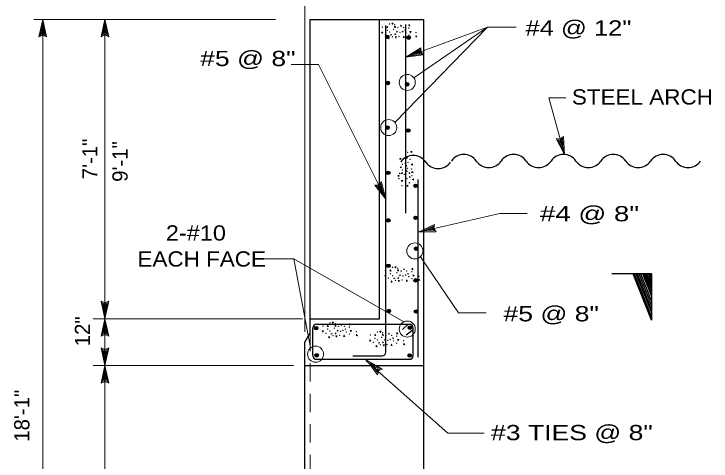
# Model space of a CAD drawing. Extents: x -28.1 to 13.9, y -16.1 to 13.9.
# Drawn here: x -18.11 to -12.4, y 6.4 to 10.06 of the extents above; entities that cross this region are included whole.
import ezdxf
from ezdxf.enums import TextEntityAlignment as Align

# ---------------------------------------------------------------- set-up
doc = ezdxf.new("R2010")
doc.units = 0
doc.header["$LTSCALE"] = 0.05
doc.linetypes.add('MEDIUM_DASHED', pattern=[4.5, 3, -1.5])
doc.layers.add('1', color=7, linetype='Continuous', lineweight=13)
doc.layers.add('2', color=7, linetype='Continuous', lineweight=13)

msp = doc.modelspace()

# ---------------------------------------------------------------- linework, layer by layer
at = {"layer": '1'}
for p, q in [((-15.72804, 7.45469), (-15.72804, 11.00169)), ((-15.96804, 10.01569), (-17.94604, 10.01569)), ((-17.87304, 10.01569), (-17.90404, 9.87169)), ((-17.87304, 3.39369), (-17.87304, 10.01569)), ((-17.87304, 10.01569), (-17.84204, 9.87169)), ((-17.36404, 10.01769), (-17.39504, 9.87369)), ((-17.36404, 10.01769), (-17.33304, 9.87369)), ((-17.87304, 9.97869), (-17.89304, 9.88469)), ((-17.87304, 9.94269), (-17.88204, 9.89769)), ((-17.87304, 9.97869), (-17.85304, 9.88469)), ((-17.87304, 9.94269), (-17.86304, 9.89769)), ((-17.36404, 9.98069), (-17.38404, 9.88669)), ((-17.36404, 9.94469), (-17.37304, 9.89969)), ((-17.36404, 9.98069), (-17.34404, 9.88669)), ((-17.36404, 9.94469), (-17.35404, 9.89969)), ((-14.90004, 9.70469), (-14.23204, 9.95169)), ((-14.83404, 9.53569), (-14.23204, 9.95169)), ((-17.87304, 9.89369), (-17.89304, 9.88469)), ((-17.87304, 9.90169), (-17.88204, 9.89769)), ((-17.86304, 9.89769), (-17.87304, 9.90169)), ((-17.85304, 9.88469), (-17.87304, 9.89369)), ((-17.36404, 9.89569), (-17.38404, 9.88669)), ((-17.36404, 9.90369), (-17.37304, 9.89969)), ((-17.35404, 9.89969), (-17.36404, 9.90369)), ((-17.34404, 9.88669), (-17.36404, 9.89569)), ((-14.90004, 9.70469), (-14.77604, 9.78369)), ((-14.86504, 9.71769), (-14.78404, 9.76869)), ((-14.78404, 9.76869), (-14.78604, 9.74669)), ((-14.90004, 9.70469), (-14.75404, 9.72569)), ((-14.86504, 9.71769), (-14.77004, 9.73169)), ((-14.83204, 9.72969), (-14.79304, 9.75469)), ((-14.83204, 9.72969), (-14.78604, 9.73669)), ((-14.79304, 9.75469), (-14.79304, 9.74469)), ((-14.79304, 9.74469), (-14.78604, 9.73669)), ((-14.78604, 9.74669), (-14.77004, 9.73169)), ((-13.73004, 9.37269), (-13.58904, 9.37269)), ((-13.61104, 8.94469), (-13.65504, 9.02969)), ((-13.65504, 9.02969), (-13.63404, 9.02669)), ((-13.62104, 8.97869), (-13.64204, 9.01969)), ((-13.64204, 9.01969), (-13.63204, 9.01869)), ((-13.63404, 9.02669), (-13.61704, 9.04069)), ((-13.63204, 9.01869), (-13.62404, 9.02469)), ((-13.62104, 8.97869), (-13.62404, 9.02469)), ((-13.61104, 8.94469), (-13.61704, 9.04069)), ((-13.60104, 8.90869), (-13.61004, 9.05569)), ((-15.06304, 8.54169), (-15.10004, 8.68469)), ((-15.06304, 8.54169), (-15.15504, 8.65669)), ((-15.13904, 8.64969), (-15.11804, 8.65069)), ((-15.08004, 8.57469), (-15.13904, 8.64969)), ((-15.12504, 8.64269), (-15.11404, 8.64369)), ((-15.09604, 8.60669), (-15.12504, 8.64269)), ((-15.11804, 8.65069), (-15.10404, 8.66769)), ((-15.11404, 8.64369), (-15.10804, 8.65169)), ((-15.09604, 8.60669), (-15.10804, 8.65169)), ((-15.08004, 8.57469), (-15.10404, 8.66769)), ((-14.79804, 8.27269), (-14.66404, 8.33469)), ((-14.76204, 8.28069), (-14.67504, 8.32169)), ((-14.76204, 8.28069), (-14.66604, 8.28269)), ((-14.72704, 8.28869), (-14.68504, 8.30869)), ((-14.72704, 8.28869), (-14.68104, 8.28969)), ((-14.68504, 8.30869), (-14.68704, 8.29769)), ((-14.68704, 8.29769), (-14.68104, 8.28969)), ((-14.67504, 8.32169), (-14.67904, 8.29969)), ((-14.67904, 8.29969), (-14.66604, 8.28269)), ((-14.79804, 8.27269), (-14.65104, 8.27469)), ((-15.81604, 8.05369), (-16.09104, 8.05369)), ((-15.68004, 7.32269), (-15.81604, 8.05369)), ((-14.91704, 7.53669), (-15.81604, 8.05369)), ((-17.36404, 7.56269), (-17.39504, 7.70669)), ((-17.36404, 7.56269), (-17.33304, 7.70669)), ((-17.36404, 7.59969), (-17.38404, 7.69369)), ((-17.38404, 7.69369), (-17.36404, 7.68469)), ((-17.36404, 7.63569), (-17.37404, 7.68069)), ((-17.37404, 7.68069), (-17.36404, 7.67669)), ((-17.36404, 7.59969), (-17.34404, 7.69369)), ((-17.36404, 7.68469), (-17.34404, 7.69369)), ((-17.36404, 7.63569), (-17.35504, 7.68069)), ((-17.36404, 7.67669), (-17.35504, 7.68069)), ((-15.74604, 7.56169), (-17.46104, 7.56169)), ((-17.36404, 7.56269), (-17.39504, 7.41869)), ((-17.36404, 7.56269), (-17.33304, 7.41869)), ((-17.36404, 7.52569), (-17.38404, 7.43169)), ((-17.36404, 7.48969), (-17.37304, 7.44469)), ((-17.36404, 7.52569), (-17.34404, 7.43169)), ((-17.36404, 7.48969), (-17.35404, 7.44469)), ((-17.36404, 7.44069), (-17.38404, 7.43169)), ((-17.36404, 7.44869), (-17.37304, 7.44469)), ((-17.35404, 7.44469), (-17.36404, 7.44869)), ((-17.34404, 7.43169), (-17.36404, 7.44069)), ((-17.36404, 7.17869), (-17.39504, 7.32269)), ((-17.36404, 7.21569), (-17.38404, 7.30969)), ((-17.38404, 7.30969), (-17.36404, 7.30069)), ((-17.36404, 7.17869), (-17.33304, 7.32269)), ((-17.36404, 7.21569), (-17.34404, 7.30969)), ((-17.36404, 7.30069), (-17.34404, 7.30969)), ((-17.36404, 7.25169), (-17.37404, 7.29669)), ((-17.37404, 7.29669), (-17.36404, 7.29269)), ((-17.36404, 7.25169), (-17.35504, 7.29669)), ((-17.36404, 7.29269), (-17.35504, 7.29669)), ((-15.21804, 7.22269), (-15.09004, 7.14969)), ((-15.21804, 7.22269), (-15.13104, 7.10369)), ((-15.19004, 7.19769), (-15.10704, 7.15069)), ((-15.19004, 7.19769), (-15.13304, 7.12069)), ((-15.81904, 7.17869), (-17.46104, 7.17869)), ((-17.36404, 7.17869), (-17.39504, 7.03469)), ((-17.36404, 7.14169), (-17.38404, 7.04769)), ((-17.36404, 7.17869), (-17.33304, 7.03469)), ((-17.36404, 7.14169), (-17.34404, 7.04769)), ((-15.16304, 7.17369), (-15.13604, 7.13769)), ((-15.16304, 7.17369), (-15.12304, 7.15169)), ((-15.13304, 7.14669), (-15.13604, 7.13769)), ((-15.12304, 7.15169), (-15.13304, 7.14669)), ((-15.12704, 7.14169), (-15.13304, 7.12069)), ((-15.10704, 7.15069), (-15.12704, 7.14169)), ((-17.36404, 7.10569), (-17.37304, 7.06069)), ((-17.36404, 7.10569), (-17.35404, 7.06069)), ((-17.36404, 7.05669), (-17.38404, 7.04769)), ((-17.36404, 7.06469), (-17.37304, 7.06069)), ((-17.35404, 7.06069), (-17.36404, 7.06469)), ((-17.34404, 7.04769), (-17.36404, 7.05669))]:
    msp.add_line(p, q, dxfattribs=at)
at = {"layer": '1', "lineweight": 25}
for p, q in [((-15.68204, 7.44769), (-15.68204, 10.01569)), ((-15.68204, 10.01569), (-14.75304, 10.01569)), ((-15.11604, 7.56169), (-15.11604, 10.01569)), ((-14.75304, 3.04369), (-14.75304, 10.01569)), ((-15.06304, 7.28869), (-15.06304, 9.96469)), ((-14.90004, 8.42769), (-14.90004, 9.97269)), ((-14.79804, 7.24769), (-14.79804, 8.70369)), ((-15.68204, 7.56169), (-15.11604, 7.56169)), ((-15.66104, 7.25969), (-15.66104, 7.48669)), ((-15.63104, 7.51669), (-14.87004, 7.51669)), ((-14.88004, 7.51669), (-14.92804, 7.47469)), ((-14.84004, 7.25969), (-14.84004, 7.48669)), ((-15.72804, 7.37069), (-15.68204, 7.44769)), ((-14.84004, 7.47169), (-14.89604, 7.42869)), ((-15.72804, 3.40969), (-15.72804, 7.37069)), ((-15.33404, 7.25869), (-15.09304, 7.25869)), ((-15.63104, 7.22969), (-14.87004, 7.22969)), ((-15.72804, 7.17869), (-14.75304, 7.17869))]:
    msp.add_line(p, q, dxfattribs=at)
at = {"layer": '1', "linetype": 'MEDIUM_DASHED'}
msp.add_line((-15.68204, 7.44769), (-15.68204, 3.40769), dxfattribs=at)
at = {"layer": '1'}
for points in [[(-17.36404, 3.39469), (-17.36404, 7.17869), (-17.36404, 7.56269), (-17.36404, 10.01769)], [(-14.99004, 9.17169), (-14.23204, 9.95169), (-13.99604, 9.95169)], [(-17.84204, 9.87169), (-17.87304, 9.88569), (-17.90404, 9.87169)], [(-17.33304, 9.87369), (-17.36404, 9.88769), (-17.39504, 9.87369)], [(-14.77604, 9.78369), (-14.77804, 9.74969), (-14.75404, 9.72569)], [(-15.06304, 8.54169), (-15.61504, 9.64569), (-15.83904, 9.64569)], [(-13.73004, 9.37269), (-13.60104, 8.90869), (-13.66904, 9.03869)], [(-13.66904, 9.03869), (-13.63604, 9.03369), (-13.61004, 9.05569)], [(-15.15504, 8.65669), (-15.12104, 8.65769), (-15.10004, 8.68469)], [(-14.79804, 8.27269), (-14.13104, 8.42469), (-13.90604, 8.42469)], [(-14.66404, 8.33469), (-14.67104, 8.30169), (-14.65104, 8.27469)], [(-14.78104, 8.06969), (-14.46804, 7.61069), (-14.24304, 7.61069)], [(-17.39504, 7.70669), (-17.36404, 7.69269), (-17.33304, 7.70669)], [(-17.33304, 7.41869), (-17.36404, 7.43269), (-17.39504, 7.41869)], [(-17.39504, 7.32269), (-17.36404, 7.30869), (-17.33304, 7.32269)], [(-15.22604, 7.22069), (-14.55504, 6.62469), (-14.25704, 6.62469)], [(-15.09004, 7.14969), (-15.12104, 7.13669), (-15.13104, 7.10369)], [(-17.33304, 7.03469), (-17.36404, 7.04869), (-17.39504, 7.03469)]]:
    msp.add_lwpolyline(points, dxfattribs=at)
at = {"layer": '1', "lineweight": 25}
for centre, radius in [((-15.05157, 9.87241), 0.01445), ((-15.05157, 9.87241), 0.01121), ((-15.05157, 9.87241), 0.00822), ((-15.05157, 9.87241), 0.00415), ((-14.87657, 9.86641), 0.01445), ((-14.87657, 9.86641), 0.01121), ((-14.87657, 9.86641), 0.00822), ((-14.87657, 9.86641), 0.00415), ((-15.04757, 9.49441), 0.01445), ((-15.04757, 9.49441), 0.01121), ((-15.04757, 9.49441), 0.00822), ((-15.04757, 9.49441), 0.00415), ((-14.88857, 9.48341), 0.01445), ((-14.88857, 9.48341), 0.01121), ((-14.88857, 9.48341), 0.00822), ((-14.88857, 9.48341), 0.00415), ((-15.04957, 9.12841), 0.01445), ((-15.04957, 9.12841), 0.01121), ((-15.04957, 9.12841), 0.00822), ((-15.04957, 9.12841), 0.00415), ((-14.87957, 9.10441), 0.01445), ((-14.87957, 9.10441), 0.01121), ((-14.87957, 9.10441), 0.00822), ((-14.87957, 9.10441), 0.00415), ((-15.04357, 8.75841), 0.01445), ((-15.04357, 8.75841), 0.01121), ((-15.04357, 8.75841), 0.00822), ((-15.04357, 8.75841), 0.00415), ((-14.81957, 8.65141), 0.01445), ((-14.81957, 8.65141), 0.01121), ((-14.81957, 8.65141), 0.00822), ((-14.81957, 8.65141), 0.00415), ((-14.81957, 8.38941), 0.01445), ((-14.81957, 8.38941), 0.01121), ((-14.81957, 8.38941), 0.00822), ((-14.81957, 8.38941), 0.00415), ((-15.04357, 8.36841), 0.01445), ((-15.04357, 8.36841), 0.01121), ((-15.04357, 8.36841), 0.00822), ((-15.04357, 8.36841), 0.00415), ((-14.81557, 8.13641), 0.01445), ((-14.81557, 8.13641), 0.01121), ((-14.81557, 8.13641), 0.00822), ((-14.81557, 8.13641), 0.00415), ((-15.04157, 7.99541), 0.01445), ((-15.04157, 7.99541), 0.01121), ((-15.04157, 7.99541), 0.00822), ((-15.04157, 7.99541), 0.00415), ((-14.81957, 7.87641), 0.01445), ((-14.81957, 7.87641), 0.01121), ((-14.81957, 7.87641), 0.00822), ((-14.81957, 7.87641), 0.00415), ((-15.03957, 7.62541), 0.01445), ((-15.03957, 7.62541), 0.01121), ((-15.03957, 7.62541), 0.00822), ((-15.03957, 7.62541), 0.00415), ((-14.81657, 7.62141), 0.01445), ((-14.81657, 7.62141), 0.01121), ((-14.81657, 7.62141), 0.00822), ((-14.81657, 7.62141), 0.00415), ((-15.63357, 7.48441), 0.01445), ((-15.63357, 7.48441), 0.01121), ((-15.63357, 7.48441), 0.00822), ((-15.63357, 7.48441), 0.00415), ((-14.86657, 7.48841), 0.01445), ((-14.86657, 7.48841), 0.01121), ((-14.86657, 7.48841), 0.00822), ((-14.86657, 7.48841), 0.00415), ((-15.62957, 7.26241), 0.01445), ((-15.62957, 7.26241), 0.01121), ((-15.62957, 7.26241), 0.00822), ((-15.62957, 7.26241), 0.00415), ((-14.86857, 7.26041), 0.01445), ((-14.86857, 7.26041), 0.01121), ((-14.86857, 7.26041), 0.00822), ((-14.86857, 7.26041), 0.00415)]:
    msp.add_circle(centre, radius, dxfattribs=at)
at = {"layer": '1'}
for centre in [(-14.88804, 9.49869), (-15.04004, 9.12869), (-14.82604, 8.11769), (-14.88804, 7.47769), (-15.63904, 7.27169)]:
    msp.add_circle(centre, 0.0658, dxfattribs=at)
at = {"layer": '1', "lineweight": 25}
for centre, radius, start, end in [((-14.42504, 8.78569), 0.12315, 34.0772, 145.92281), ((-14.01704, 8.78569), 0.12315, 34.0772, 145.92281), ((-13.60904, 8.78569), 0.12315, 34.0772, 145.92281), ((-13.20104, 8.78569), 0.12315, 34.0772, 145.92281), ((-12.79304, 8.78569), 0.12315, 34.0772, 145.92281), ((-14.83904, 8.77769), 0.12315, 34.0772, 145.92281), ((-14.22104, 8.92369), 0.12315, 214.0772, 325.92281), ((-13.81304, 8.92369), 0.12315, 214.0772, 325.92281), ((-13.40504, 8.92369), 0.12315, 214.0772, 325.92281), ((-12.99704, 8.92369), 0.12315, 214.0772, 325.92281), ((-12.58904, 8.92369), 0.12315, 214.0772, 325.92281), ((-14.63504, 8.91569), 0.12315, 214.0772, 325.92281), ((-15.63104, 7.48669), 0.03, 90, 180), ((-14.87004, 7.48669), 0.03, 0, 90), ((-15.63104, 7.25969), 0.03, 180, 270), ((-15.09304, 7.28869), 0.03, 270, 0), ((-14.87004, 7.25969), 0.03, 270, 0)]:
    msp.add_arc(centre, radius, start, end, dxfattribs=at)
at = {"layer": '2'}
for p, q in [((-14.94404, 9.96269), (-14.93804, 9.96769)), ((-14.94104, 8.79969), (-14.94604, 8.80569)), ((-14.91904, 7.96669), (-14.91304, 7.97169)), ((-15.43104, 7.51269), (-15.42504, 7.51769)), ((-15.04304, 7.43869), (-15.03704, 7.44369))]:
    msp.add_line(p, q, dxfattribs=at)
at = {"layer": '2', "lineweight": 25}
for p, q in [((-12.88804, 7.92969), (-13.21204, 7.92969)), ((-12.88804, 7.58169), (-13.02604, 7.92969)), ((-12.88804, 7.61469), (-13.01304, 7.92969)), ((-12.88804, 7.63769), (-13.00404, 7.92969)), ((-12.88804, 7.67369), (-12.99004, 7.92969)), ((-12.88804, 7.70769), (-12.97604, 7.92969)), ((-12.88804, 7.74869), (-12.96004, 7.92969)), ((-12.88804, 7.77569), (-12.94904, 7.92969)), ((-12.88804, 7.80769), (-12.93704, 7.92969)), ((-12.88804, 7.83669), (-12.92504, 7.92969)), ((-12.88804, 7.86569), (-12.91404, 7.92969)), ((-12.88804, 7.88569), (-12.90604, 7.92969)), ((-12.88804, 7.91269), (-12.89504, 7.92969))]:
    msp.add_line(p, q, dxfattribs=at)
at = {"layer": '2'}
for points in [[(-15.05104, 9.95969), (-15.05604, 9.94969), (-15.04604, 9.94869), (-15.05404, 9.95969)], [(-15.01004, 9.97469), (-15.01504, 9.98369), (-15.00404, 9.98369), (-15.01004, 9.97269)], [(-14.98904, 9.96069), (-14.99404, 9.95069), (-14.98304, 9.94969), (-14.99104, 9.96069)], [(-14.93804, 9.96769), (-14.93604, 9.96069), (-14.94404, 9.96069)], [(-14.87104, 9.97269), (-14.87604, 9.96269), (-14.86604, 9.96169), (-14.87404, 9.97269)], [(-15.09304, 9.90369), (-15.09804, 9.91169), (-15.08704, 9.91169), (-15.09304, 9.90169)], [(-15.02404, 9.88869), (-15.01904, 9.89169), (-15.01504, 9.88869), (-15.02704, 9.88669)], [(-14.93104, 9.91469), (-14.92804, 9.91869), (-14.92304, 9.91469), (-14.93004, 9.91369)], [(-14.91704, 9.87669), (-14.92204, 9.86669), (-14.91204, 9.86569), (-14.92004, 9.87669)], [(-14.91104, 9.92769), (-14.90604, 9.92969), (-14.90304, 9.92369), (-14.91104, 9.92669)], [(-14.86304, 9.90769), (-14.86804, 9.91569), (-14.85704, 9.91569), (-14.86304, 9.90569)], [(-14.81404, 9.88369), (-14.81904, 9.87369), (-14.80904, 9.87269), (-14.81604, 9.88369)], [(-15.04104, 9.86769), (-15.04604, 9.85769), (-15.03604, 9.85669), (-15.04404, 9.86769)], [(-14.98204, 9.86269), (-14.98704, 9.87169), (-14.97604, 9.87169), (-14.98204, 9.86169)], [(-14.86204, 8.92969), (-14.85204, 8.92469), (-14.85104, 8.93469), (-14.86204, 8.92769)], [(-14.95104, 8.87269), (-14.94104, 8.86769), (-14.94004, 8.87769), (-14.95104, 8.86969)], [(-14.88604, 8.88069), (-14.89404, 8.87569), (-14.89404, 8.88669), (-14.88404, 8.88069)], [(-14.94604, 8.80569), (-14.93904, 8.80769), (-14.93904, 8.79969)], [(-14.90604, 8.83269), (-14.90804, 8.83769), (-14.90204, 8.84069), (-14.90504, 8.83269)], [(-14.89304, 8.81269), (-14.89704, 8.81569), (-14.89304, 8.82069), (-14.89204, 8.81369)], [(-14.85504, 8.82669), (-14.84504, 8.82169), (-14.84404, 8.83169), (-14.85504, 8.82369)], [(-14.95304, 8.73369), (-14.96204, 8.72869), (-14.96204, 8.73969), (-14.95104, 8.73369)], [(-14.93904, 8.75469), (-14.92904, 8.74969), (-14.92804, 8.76069), (-14.93904, 8.75269)], [(-14.84104, 8.76169), (-14.85004, 8.75669), (-14.85004, 8.76769), (-14.84004, 8.76169)], [(-14.93804, 8.69269), (-14.92804, 8.68769), (-14.92704, 8.69769), (-14.93804, 8.68969)], [(-14.86704, 8.71969), (-14.87004, 8.72469), (-14.86704, 8.72869), (-14.86504, 8.71669)], [(-14.84604, 8.70269), (-14.83604, 8.69769), (-14.83504, 8.70769), (-14.84604, 8.69969)], [(-14.88204, 8.65069), (-14.89004, 8.64569), (-14.89004, 8.65669), (-14.88004, 8.65069)], [(-15.02604, 7.96369), (-15.03104, 7.95369), (-15.02104, 7.95269), (-15.02904, 7.96369)], [(-14.98504, 7.97869), (-14.99004, 7.98769), (-14.97904, 7.98769), (-14.98504, 7.97669)], [(-14.96404, 7.96469), (-14.96904, 7.95469), (-14.95804, 7.95369), (-14.96604, 7.96469)], [(-14.91304, 7.97169), (-14.91104, 7.96469), (-14.91904, 7.96469)], [(-14.84604, 7.97669), (-14.85104, 7.96669), (-14.84104, 7.96569), (-14.84904, 7.97669)], [(-15.06804, 7.90769), (-15.07304, 7.91569), (-15.06204, 7.91569), (-15.06804, 7.90569)], [(-14.99904, 7.89269), (-14.99404, 7.89569), (-14.99004, 7.89269), (-15.00204, 7.89069)], [(-14.90604, 7.91869), (-14.90304, 7.92269), (-14.89804, 7.91869), (-14.90504, 7.91769)], [(-14.89204, 7.88069), (-14.89704, 7.87069), (-14.88704, 7.86969), (-14.89504, 7.88069)], [(-14.88604, 7.93169), (-14.88104, 7.93369), (-14.87804, 7.92769), (-14.88604, 7.93069)], [(-14.83804, 7.91169), (-14.84304, 7.91969), (-14.83204, 7.91969), (-14.83804, 7.90969)], [(-14.78904, 7.88769), (-14.79404, 7.87769), (-14.78404, 7.87669), (-14.79104, 7.88769)], [(-15.01604, 7.87169), (-15.02104, 7.86169), (-15.01104, 7.86069), (-15.01904, 7.87169)], [(-14.95704, 7.86669), (-14.96204, 7.87569), (-14.95104, 7.87569), (-14.95704, 7.86569)], [(-15.53804, 7.50969), (-15.54304, 7.49969), (-15.53304, 7.49869), (-15.54104, 7.50969)], [(-15.49704, 7.52469), (-15.50204, 7.53369), (-15.49104, 7.53369), (-15.49704, 7.52269)], [(-15.47604, 7.51069), (-15.48104, 7.50069), (-15.47004, 7.49969), (-15.47804, 7.51069)], [(-15.42504, 7.51769), (-15.42304, 7.51069), (-15.43104, 7.51069)], [(-15.39804, 7.47769), (-15.39304, 7.47969), (-15.39004, 7.47369), (-15.39804, 7.47669)], [(-15.35804, 7.52269), (-15.36304, 7.51269), (-15.35304, 7.51169), (-15.36104, 7.52269)], [(-15.58004, 7.45369), (-15.58504, 7.46169), (-15.57404, 7.46169), (-15.58004, 7.45169)], [(-15.51104, 7.43869), (-15.50604, 7.44169), (-15.50204, 7.43869), (-15.51404, 7.43669)], [(-15.46904, 7.41269), (-15.47404, 7.42169), (-15.46304, 7.42169), (-15.46904, 7.41169)], [(-15.41804, 7.46469), (-15.41504, 7.46869), (-15.41004, 7.46469), (-15.41704, 7.46369)], [(-15.40404, 7.42669), (-15.40904, 7.41669), (-15.39904, 7.41569), (-15.40704, 7.42669)], [(-15.35004, 7.45769), (-15.35504, 7.46569), (-15.34404, 7.46569), (-15.35004, 7.45569)], [(-15.30104, 7.43369), (-15.30604, 7.42369), (-15.29604, 7.42269), (-15.30304, 7.43369)], [(-15.15004, 7.43569), (-15.15504, 7.42569), (-15.14504, 7.42469), (-15.15304, 7.43569)], [(-15.10904, 7.45069), (-15.11404, 7.45969), (-15.10304, 7.45969), (-15.10904, 7.44869)], [(-15.08804, 7.43669), (-15.09304, 7.42669), (-15.08204, 7.42569), (-15.09004, 7.43669)], [(-15.03704, 7.44369), (-15.03504, 7.43669), (-15.04304, 7.43669)], [(-14.97004, 7.44869), (-14.97504, 7.43869), (-14.96504, 7.43769), (-14.97304, 7.44869)], [(-15.52804, 7.41769), (-15.53304, 7.40769), (-15.52304, 7.40669), (-15.53104, 7.41769)], [(-15.19204, 7.37969), (-15.19704, 7.38769), (-15.18604, 7.38769), (-15.19204, 7.37769)], [(-15.12304, 7.36469), (-15.11804, 7.36769), (-15.11404, 7.36469), (-15.12604, 7.36269)], [(-15.03004, 7.39069), (-15.02704, 7.39469), (-15.02204, 7.39069), (-15.02904, 7.38969)], [(-15.01004, 7.40369), (-15.00504, 7.40569), (-15.00204, 7.39969), (-15.01004, 7.40269)], [(-14.96204, 7.38369), (-14.96704, 7.39169), (-14.95604, 7.39169), (-14.96204, 7.38169)], [(-15.14004, 7.34369), (-15.14504, 7.33369), (-15.13504, 7.33269), (-15.14304, 7.34369)], [(-15.08104, 7.33869), (-15.08604, 7.34769), (-15.07504, 7.34769), (-15.08104, 7.33769)], [(-15.01604, 7.35269), (-15.02104, 7.34269), (-15.01104, 7.34169), (-15.01904, 7.35269)], [(-14.91304, 7.35969), (-14.91804, 7.34969), (-14.90804, 7.34869), (-14.91504, 7.35969)]]:
    msp.add_lwpolyline(points, dxfattribs=at)
for points in [[(-14.99104, 9.88869), (-14.98604, 9.89669), (-14.98304, 9.89069)], [(-14.97604, 9.90969), (-14.97104, 9.91869), (-14.96804, 9.91269)], [(-14.88804, 8.76769), (-14.89704, 8.77269), (-14.89104, 8.77569)], [(-14.86704, 8.75269), (-14.87504, 8.75769), (-14.86904, 8.76069)], [(-14.96604, 7.89269), (-14.96104, 7.90069), (-14.95804, 7.89469)], [(-14.95104, 7.91369), (-14.94604, 7.92269), (-14.94304, 7.91669)], [(-15.47804, 7.43869), (-15.47304, 7.44669), (-15.47004, 7.44069)], [(-15.46304, 7.45969), (-15.45804, 7.46869), (-15.45504, 7.46269)], [(-15.09004, 7.36469), (-15.08504, 7.37269), (-15.08204, 7.36669)], [(-15.07504, 7.38569), (-15.07004, 7.39469), (-15.06704, 7.38869)]]:
    msp.add_lwpolyline(points, close=True, dxfattribs=at)
at = {"layer": '2', "lineweight": 25}
msp.add_lwpolyline([(-12.88804, 7.92969), (-12.88804, 7.55069), (-13.03804, 7.92969)], dxfattribs=at)
at = {"layer": '2'}
for centre in [(-15.09204, 9.95181), (-15.03379, 9.97856), (-14.99854, 9.93481), (-14.99104, 9.97181), (-14.96329, 9.95006), (-14.91704, 9.94906), (-14.87579, 9.94331), (-15.06754, 9.89281), (-15.05229, 9.92656), (-15.03304, 9.91131), (-14.95554, 9.87506), (-14.94804, 9.90956), (-14.90004, 9.90381), (-14.87479, 9.88606), (-14.81754, 9.90556), (-15.00954, 9.87256), (-14.88392, 8.92619), (-14.92167, 8.86794), (-14.86442, 8.86894), (-14.92742, 8.82669), (-14.88792, 8.79569), (-14.88217, 8.84369), (-14.95017, 8.75269), (-14.92842, 8.78044), (-14.91317, 8.74519), (-14.85342, 8.78819), (-14.85092, 8.73419), (-14.95692, 8.70994), (-14.90492, 8.69144), (-14.88967, 8.71069), (-14.87117, 8.67619), (-14.93017, 8.65169), (-15.06704, 7.95581), (-15.00879, 7.98256), (-14.97354, 7.93881), (-14.96604, 7.97581), (-14.93829, 7.95406), (-14.89204, 7.95306), (-14.85079, 7.94731), (-15.04254, 7.89681), (-15.02729, 7.93056), (-15.00804, 7.91531), (-14.98454, 7.87656), (-14.93054, 7.87906), (-14.92304, 7.91356), (-14.87504, 7.90781), (-14.84979, 7.89006), (-14.79254, 7.90956), (-15.57904, 7.50181), (-15.53929, 7.47656), (-15.52079, 7.52856), (-15.48554, 7.48481), (-15.47804, 7.52181), (-15.45029, 7.50006), (-15.40404, 7.49906), (-15.36279, 7.49331), (-15.55454, 7.44281), (-15.52004, 7.46131), (-15.49654, 7.42256), (-15.44254, 7.42506), (-15.43504, 7.45956), (-15.38704, 7.45381), (-15.36179, 7.43606), (-15.30454, 7.45556), (-15.19104, 7.42781), (-15.13279, 7.45456), (-15.09004, 7.44781), (-15.06229, 7.42606), (-15.01604, 7.42506), (-15.16654, 7.36881), (-15.15129, 7.40256), (-15.13204, 7.38731), (-15.09754, 7.41081), (-15.04704, 7.38556), (-14.99904, 7.37981), (-14.97479, 7.41931), (-14.91654, 7.38156), (-15.10854, 7.34856), (-15.05454, 7.35106), (-14.97379, 7.36206)]:
    msp.add_circle(centre, 0.00162, dxfattribs=at)

# ---------------------------------------------------------------- texts
at = {"layer": '1'}
for s, width, p in [('#4 @ 12"', 1.25, (-13.92004, 9.88269)), ('#5 @ 8"', 1.3, (-16.58404, 9.63269)), ('STEEL ARCH', 1.1, (-13.54004, 9.31769)), ('#4 @ 8"', 1.35, (-13.80104, 8.36069)), ('#5 @ 8"', 1.3, (-14.10004, 7.54069)), ('#3 TIES @ 8"', 1.3, (-14.20204, 6.56669))]:
    msp.add_text(s, height=0.125, dxfattribs=dict(at, width=width)).set_placement(p)
for s, p in [('7\'-1"', (-17.42504, 8.87196)), ('9\'-1"', (-17.17804, 8.8505)), ('12"', (-17.48504, 7.4587)), ('18\'-1"', (-17.98204, 6.7669))]:
    msp.add_text(s, height=0.125, rotation=90, dxfattribs=at).set_placement(p, align=Align.CENTER)
at = {"layer": '1', "width": 1.15}
msp.add_text('2-#10', height=0.125, dxfattribs=at).set_placement((-16.61896, 8.20269), align=Align.CENTER)
at = {"layer": '1', "width": 1.1}
msp.add_text('EACH FACE', height=0.125, dxfattribs=at).set_placement((-16.04518, 7.98969), align=Align.RIGHT)

doc.saveas('drawing.dxf')
